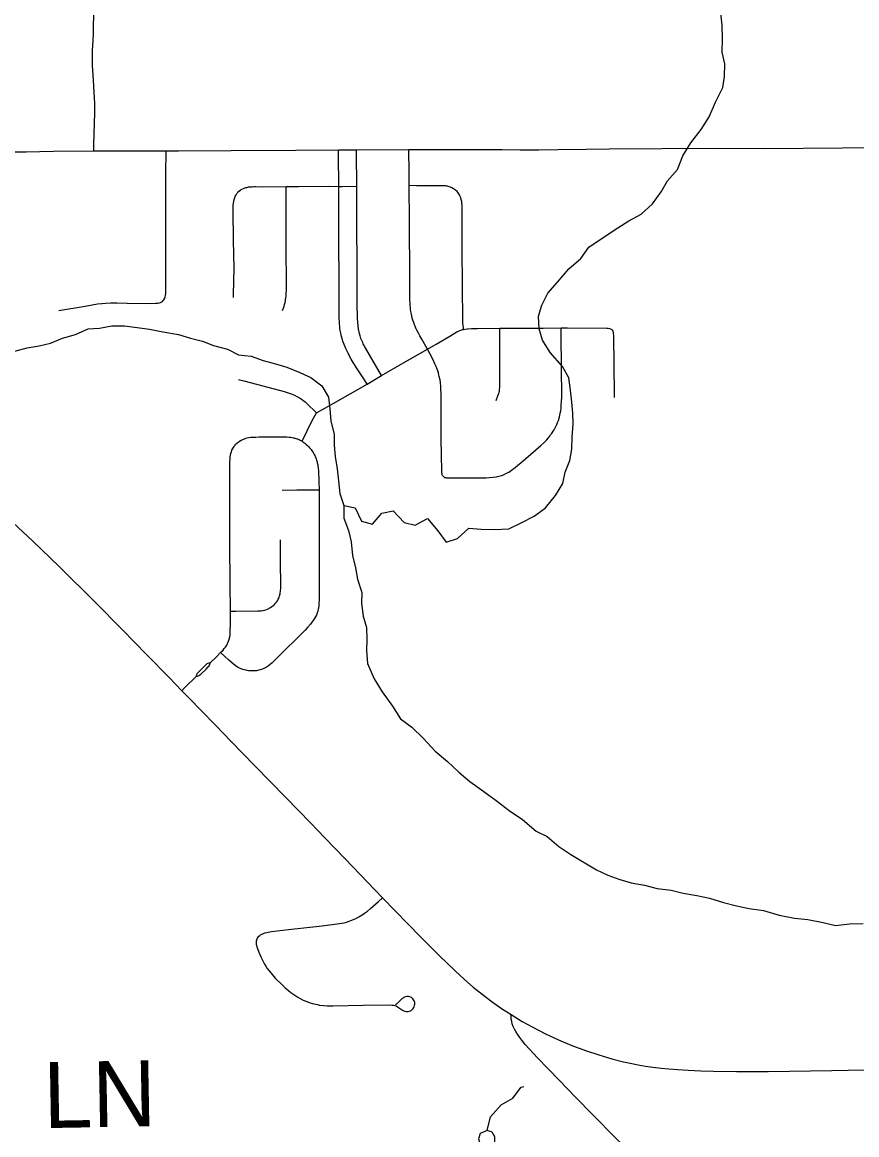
# Model space of a CAD drawing. Extents: x 0 to 34, y 0 to 22.
# Drawn here: x 24.284 to 25.003, y 13.986 to 14.945 of the extents above; entities that cross this region are included whole.
import ezdxf

# ---------------------------------------------------------------- set-up
doc = ezdxf.new("R2010")
doc.units = 0
for name, color, linetype in [('GM_X_County_Road', 7, 'Continuous'), ('GM_X_County_Road_Text', 7, 'Continuous'), ('GM_X_Minor_Lake', 7, 'Continuous'), ('GM_X_Minor_River', 7, 'Continuous'), ('GM_X_State_Route', 7, 'Continuous'), ('GM_X_Township_Road', 7, 'Continuous')]:
    doc.layers.add(name, color=color, linetype=linetype)

msp = doc.modelspace()

# ---------------------------------------------------------------- linework, layer by layer
at = {"layer": 'GM_X_County_Road'}
msp.add_lwpolyline([(24.80457, 13.97386), (24.79456, 13.98403), (24.77577, 14.00299), (24.76063, 14.01855), (24.74635, 14.03327), (24.72773, 14.05246), (24.71728, 14.06389), (24.71509, 14.0665), (24.71251, 14.06988), (24.7105, 14.07286), (24.70904, 14.07511), (24.70787, 14.07717), (24.70687, 14.07942), (24.70607, 14.08178), (24.70558, 14.08381), (24.70525, 14.08589), (24.70502, 14.08982)], dxfattribs=at)
at = {"layer": 'GM_X_Minor_Lake'}
msp.add_lwpolyline([(24.68006, 13.97726), (24.68161, 13.97588), (24.68426, 13.97514), (24.68578, 13.97477), (24.68842, 13.97631), (24.69104, 13.97974), (24.69101, 13.98429), (24.6887, 13.98844), (24.68453, 13.98993), (24.67849, 13.98723), (24.67702, 13.98267), (24.67796, 13.97992)], dxfattribs=at)
at = {"layer": 'GM_X_Minor_River'}
for points in [[(24.56103, 14.52851), (24.57089, 14.52632), (24.57628, 14.51498), (24.58576, 14.5124), (24.59363, 14.52194), (24.60346, 14.52391), (24.613, 14.51375), (24.62248, 14.51155), (24.63303, 14.51731), (24.64182, 14.50676), (24.64909, 14.49696), (24.6589, 14.50007), (24.66868, 14.50887), (24.67928, 14.50819), (24.69101, 14.5079), (24.70312, 14.50837), (24.71368, 14.51338), (24.72499, 14.51915), (24.73477, 14.52643), (24.74339, 14.53712), (24.74974, 14.5474), (24.75156, 14.55727), (24.75564, 14.56716), (24.75745, 14.57703), (24.75775, 14.58727), (24.75842, 14.59865), (24.75834, 14.60813), (24.75751, 14.6176), (24.75629, 14.62783), (24.75469, 14.63843), (24.74932, 14.64825), (24.73862, 14.6603), (24.73211, 14.67086), (24.72938, 14.6807), (24.72853, 14.69169), (24.73148, 14.70119), (24.7367, 14.71147), (24.74495, 14.72101), (24.7547, 14.73246), (24.76523, 14.74126), (24.77196, 14.75117), (24.7938, 14.76574), (24.8066, 14.7738), (24.81715, 14.77957), (24.82692, 14.78837), (24.83441, 14.79866), (24.83964, 14.80818), (24.84826, 14.8181), (24.85309, 14.82989), (24.85981, 14.84094), (24.8688, 14.85238), (24.87553, 14.86343), (24.88111, 14.87598), (24.88744, 14.88854), (24.88888, 14.89803), (24.88917, 14.90903), (24.88682, 14.91925), (24.88711, 14.93063), (24.88701, 14.94238), (24.88579, 14.95261)], [(24.27763, 14.66131), (24.2882, 14.66443), (24.29841, 14.66602), (24.30823, 14.66837), (24.31879, 14.67262), (24.32975, 14.67574), (24.34068, 14.68076), (24.35052, 14.68121), (24.3611, 14.68319), (24.37207, 14.68327), (24.38306, 14.68184), (24.39367, 14.6804), (24.40504, 14.67822), (24.41869, 14.67567), (24.42893, 14.67271), (24.43917, 14.67014), (24.44866, 14.66642), (24.4608, 14.6631), (24.4703, 14.65824), (24.48128, 14.65719), (24.49153, 14.65348), (24.50215, 14.65052), (24.51202, 14.64757), (24.52303, 14.6431), (24.53253, 14.63862), (24.54204, 14.63149), (24.5478, 14.62168), (24.54901, 14.61183), (24.54986, 14.60122), (24.55259, 14.58987), (24.55267, 14.58039), (24.55351, 14.57054), (24.55511, 14.55994), (24.55632, 14.54971), (24.55754, 14.53872), (24.56103, 14.52851), (24.56112, 14.51752), (24.56499, 14.50693), (24.56734, 14.49709), (24.56857, 14.48535), (24.57092, 14.47475), (24.57289, 14.46491), (24.57639, 14.45356), (24.57609, 14.44408), (24.57769, 14.4331), (24.58041, 14.42326), (24.58087, 14.41303), (24.58057, 14.40355), (24.58142, 14.39218), (24.5872, 14.37895), (24.5941, 14.36801), (24.6029, 14.35557), (24.6098, 14.34463), (24.6197, 14.3375), (24.62924, 14.32809), (24.63955, 14.3168), (24.65022, 14.30778), (24.66013, 14.29876), (24.66966, 14.29049), (24.68146, 14.28186), (24.69211, 14.27436), (24.70354, 14.26572), (24.71495, 14.25785), (24.72677, 14.2477), (24.73627, 14.24323)], [(24.73627, 14.24323), (24.74618, 14.23458), (24.75645, 14.22784), (24.77851, 14.21436), (24.78838, 14.20988), (24.79787, 14.20654), (24.8085, 14.20321), (24.81986, 14.2014), (24.83086, 14.19846), (24.84299, 14.19703), (24.85323, 14.19446), (24.86498, 14.19227), (24.87597, 14.19008), (24.88811, 14.18638), (24.89911, 14.18344), (24.9101, 14.18124), (24.92261, 14.17944), (24.93589, 14.17538), (24.94915, 14.17282), (24.96052, 14.17177), (24.97378, 14.16922), (24.9844, 14.16665), (24.9965, 14.16788), (25.00823, 14.16835)], [(24.68453, 13.98993), (24.68746, 14.00171), (24.69647, 14.01201), (24.70664, 14.01778), (24.71375, 14.02731), (24.71602, 14.02771)]]:
    msp.add_lwpolyline(points, dxfattribs=at)
at = {"layer": 'GM_X_State_Route'}
for points in [[(24.27612, 14.51342), (24.29281, 14.49786), (24.3158, 14.47575), (24.34676, 14.44528), (24.37013, 14.4215), (24.39132, 14.39977), (24.41042, 14.38035), (24.42148, 14.36883), (24.4285, 14.36151), (24.43715, 14.35259), (24.45065, 14.33884), (24.46364, 14.32546), (24.48432, 14.30425), (24.51078, 14.27725), (24.53261, 14.25462), (24.54452, 14.24219)], [(24.54452, 14.24219), (24.56203, 14.2239), (24.59426, 14.19023), (24.62702, 14.15663), (24.64335, 14.14046), (24.65678, 14.12754), (24.66497, 14.11996), (24.67247, 14.11347), (24.68019, 14.10726), (24.68875, 14.10088), (24.69689, 14.09512), (24.70502, 14.08982), (24.71456, 14.08392), (24.7232, 14.07907), (24.73475, 14.07312), (24.74599, 14.0679), (24.75744, 14.06317), (24.76908, 14.05889), (24.78051, 14.05511), (24.79185, 14.05173), (24.80189, 14.04917), (24.80772, 14.04786), (24.81447, 14.04645), (24.82096, 14.04538), (24.82721, 14.04448), (24.83445, 14.04357), (24.8409, 14.04298), (24.8486, 14.04241), (24.8576, 14.04188), (24.8685, 14.04141), (24.87932, 14.04106), (24.89919, 14.04072), (24.92652, 14.04081), (24.9812, 14.04166), (25.05143, 14.04294)]]:
    msp.add_lwpolyline(points, dxfattribs=at)
at = {"layer": 'GM_X_Township_Road'}
for points in [[(24.34552, 14.834), (24.34568, 14.8396), (24.34647, 14.86689), (24.34647, 14.87133), (24.3464, 14.87497), (24.34621, 14.87976), (24.34498, 14.89957), (24.34475, 14.90332), (24.34456, 14.90753), (24.3445, 14.90994), (24.34445, 14.91319), (24.34446, 14.91561), (24.34451, 14.91753), (24.34463, 14.92042), (24.34502, 14.92876), (24.34526, 14.93517), (24.34546, 14.94365), (24.34588, 14.95475)], [(24.15556, 14.83308), (24.18625, 14.83308), (24.25271, 14.83314), (24.26824, 14.83324), (24.28747, 14.83335), (24.311, 14.83371), (24.34552, 14.834)], [(24.34552, 14.834), (24.365, 14.83416), (24.3942, 14.83409), (24.40797, 14.83397)], [(24.40471, 14.70439), (24.4054, 14.70508), (24.40588, 14.70567), (24.40666, 14.70704), (24.40708, 14.70812), (24.40747, 14.70972), (24.40761, 14.71081), (24.40769, 14.71218), (24.40772, 14.71545), (24.40778, 14.72412), (24.4077, 14.75948), (24.40757, 14.78273), (24.40775, 14.81204), (24.40775, 14.81696), (24.40793, 14.83114), (24.40797, 14.83397)], [(24.40797, 14.83397), (24.41868, 14.83404), (24.46404, 14.83426), (24.5197, 14.83467), (24.55652, 14.83483)], [(24.55652, 14.83483), (24.57196, 14.83498), (24.61685, 14.83521)], [(24.58094, 14.63311), (24.57867, 14.63664), (24.57199, 14.64704), (24.57008, 14.65005), (24.56916, 14.65155), (24.56744, 14.65444), (24.56584, 14.65726), (24.56458, 14.65968), (24.56271, 14.66364), (24.56119, 14.66712), (24.56017, 14.67004), (24.55981, 14.67121), (24.55927, 14.67313), (24.55903, 14.67408), (24.55834, 14.67702), (24.55793, 14.67922), (24.5576, 14.68162), (24.55742, 14.68321), (24.5573, 14.68447), (24.55714, 14.68696), (24.55702, 14.68922), (24.55693, 14.69192), (24.55684, 14.69619), (24.55686, 14.71306), (24.55678, 14.76446), (24.5566, 14.80349), (24.55653, 14.83073), (24.55652, 14.83483)], [(24.59352, 14.64036), (24.59151, 14.64384), (24.58, 14.66375), (24.57918, 14.66519), (24.57852, 14.66639), (24.57778, 14.66787), (24.57727, 14.66889), (24.57695, 14.66956), (24.57645, 14.67063), (24.57598, 14.67169), (24.57567, 14.67249), (24.57526, 14.67364), (24.57496, 14.67457), (24.57443, 14.67658), (24.5737, 14.68027), (24.57322, 14.68346), (24.57292, 14.68614), (24.57268, 14.68995), (24.5724, 14.70213), (24.57206, 14.8035), (24.57197, 14.83206), (24.57196, 14.83498)], [(24.61685, 14.83521), (24.63145, 14.83517), (24.65941, 14.83516), (24.69734, 14.83513), (24.71287, 14.83505), (24.72896, 14.83493), (24.74549, 14.83513), (24.76968, 14.83549), (24.78957, 14.83568), (24.8805, 14.83633), (24.92309, 14.83613), (24.99049, 14.83667), (25.01908, 14.83689), (25.0932, 14.83659), (25.1496, 14.83666), (25.1554, 14.83676)], [(24.64651, 14.55366), (24.6461, 14.55428), (24.64576, 14.55501), (24.64556, 14.55577), (24.64545, 14.55658), (24.64541, 14.55724), (24.64539, 14.55802), (24.64485, 14.58591), (24.64476, 14.60148), (24.64469, 14.6133), (24.64472, 14.62117), (24.64471, 14.62543), (24.64466, 14.62804), (24.64451, 14.63123), (24.64421, 14.63423), (24.64385, 14.63667), (24.64366, 14.63767), (24.64323, 14.63957), (24.64291, 14.64088), (24.64243, 14.64266), (24.6419, 14.6444), (24.64136, 14.64595), (24.6405, 14.64816), (24.63949, 14.65046), (24.63787, 14.65398), (24.63548, 14.65883), (24.63312, 14.66324), (24.62818, 14.67165), (24.62649, 14.67458), (24.62519, 14.67688), (24.62379, 14.67962), (24.623, 14.68129), (24.62235, 14.68286), (24.62181, 14.68417), (24.62114, 14.68606), (24.62042, 14.68822), (24.6199, 14.68995), (24.61944, 14.692), (24.61896, 14.69442), (24.61876, 14.69561), (24.61853, 14.69726), (24.61839, 14.69847), (24.61819, 14.70134), (24.61797, 14.70701), (24.61789, 14.71047), (24.61789, 14.72697), (24.61776, 14.74613), (24.61765, 14.75163), (24.61758, 14.76702), (24.61758, 14.7732), (24.61732, 14.80408), (24.61719, 14.81978), (24.61695, 14.83083), (24.61685, 14.83521)], [(24.46598, 14.70778), (24.46602, 14.70965), (24.4663, 14.72205), (24.4665, 14.73266), (24.4662, 14.74511), (24.46606, 14.75686), (24.4657, 14.78234), (24.46571, 14.78351), (24.46575, 14.78586), (24.4658, 14.78717), (24.46589, 14.7887), (24.46614, 14.7906), (24.46643, 14.79209), (24.46698, 14.79385), (24.46771, 14.79541), (24.46822, 14.79627), (24.46885, 14.79721), (24.46959, 14.79812), (24.47067, 14.79923), (24.47186, 14.80015), (24.4726, 14.80067), (24.47326, 14.80108), (24.47449, 14.8017), (24.47512, 14.80195), (24.47597, 14.80224), (24.47664, 14.80244), (24.4774, 14.80263), (24.4782, 14.80279), (24.47893, 14.80292), (24.48073, 14.80311), (24.48198, 14.80319), (24.48353, 14.80322), (24.48493, 14.80322), (24.49132, 14.80314), (24.5112, 14.80334), (24.52195, 14.80345), (24.54744, 14.8035), (24.5566, 14.80349), (24.55976, 14.80349), (24.57206, 14.8035)], [(24.50814, 14.69663), (24.50871, 14.69806), (24.50922, 14.69946), (24.50949, 14.70031), (24.5099, 14.70173), (24.51014, 14.70264), (24.51033, 14.70349), (24.51063, 14.70485), (24.51087, 14.70622), (24.511, 14.70719), (24.51119, 14.7088), (24.51127, 14.70962), (24.51136, 14.71076), (24.51157, 14.71435), (24.51167, 14.7178), (24.51143, 14.7522), (24.51133, 14.76734), (24.5112, 14.80047), (24.5112, 14.80334)], [(24.6642, 14.68021), (24.66396, 14.6817), (24.66364, 14.68365), (24.66348, 14.68594), (24.66308, 14.71965), (24.66304, 14.74756), (24.66289, 14.76362), (24.66291, 14.78), (24.66282, 14.78685), (24.66268, 14.789), (24.66254, 14.79033), (24.66219, 14.79211), (24.66178, 14.79349), (24.66104, 14.7953), (24.66051, 14.7963), (24.65943, 14.79787), (24.65848, 14.7989), (24.65705, 14.80024), (24.65629, 14.80083), (24.65557, 14.80134), (24.65407, 14.80222), (24.6528, 14.80283), (24.65185, 14.80319), (24.65036, 14.80355), (24.64955, 14.80371), (24.64865, 14.80381), (24.64797, 14.80387), (24.64664, 14.80392), (24.6237, 14.80404), (24.61732, 14.80408)], [(24.31556, 14.69662), (24.33828, 14.70035), (24.34875, 14.70216), (24.35257, 14.70263), (24.35602, 14.70289), (24.36016, 14.70303), (24.36549, 14.70306), (24.37447, 14.7028)], [(24.37447, 14.7028), (24.39141, 14.70264), (24.39882, 14.70267), (24.39965, 14.7027), (24.40086, 14.70281), (24.40222, 14.70311), (24.40301, 14.7034), (24.40365, 14.70371), (24.40471, 14.70439)], [(24.52497, 14.58385), (24.53383, 14.60172), (24.53741, 14.60826), (24.55166, 14.61622), (24.58094, 14.63311), (24.59352, 14.64036), (24.61591, 14.65328), (24.63312, 14.66324), (24.64064, 14.66758), (24.65238, 14.67451), (24.65831, 14.67801), (24.66033, 14.67903), (24.66163, 14.67955), (24.66358, 14.68009), (24.6642, 14.68021), (24.66525, 14.68042), (24.66742, 14.6807), (24.66822, 14.68076), (24.67101, 14.6809), (24.676, 14.68107), (24.6955, 14.68117), (24.69776, 14.68119), (24.71517, 14.6813), (24.73256, 14.68136), (24.74821, 14.68149), (24.75368, 14.68154), (24.7874, 14.68129), (24.78872, 14.68114), (24.78977, 14.68091), (24.79075, 14.68057), (24.79169, 14.67999)], [(24.64651, 14.55366), (24.6471, 14.55307), (24.64774, 14.55271), (24.64873, 14.5525), (24.64955, 14.55243), (24.65028, 14.5524), (24.65119, 14.55238), (24.65348, 14.55236), (24.66616, 14.55233), (24.6836, 14.55236), (24.6865, 14.5525), (24.68974, 14.55274), (24.69223, 14.55309), (24.69459, 14.5536), (24.69666, 14.55425), (24.69855, 14.55497), (24.70066, 14.55596), (24.70303, 14.55732), (24.70548, 14.55894), (24.70858, 14.56123), (24.71091, 14.56313), (24.71347, 14.56531), (24.73055, 14.58008), (24.73315, 14.58252), (24.7357, 14.58509), (24.73701, 14.58658), (24.73835, 14.58822), (24.73913, 14.58921), (24.73981, 14.59013), (24.74052, 14.59119), (24.74135, 14.59246), (24.74214, 14.59371), (24.74281, 14.59484), (24.74371, 14.59659), (24.74449, 14.59833), (24.74517, 14.59999), (24.74575, 14.60171), (24.74673, 14.60473), (24.7471, 14.60627), (24.74746, 14.60806), (24.74779, 14.60998), (24.74805, 14.61228), (24.74831, 14.61514), (24.7485, 14.61807), (24.74867, 14.62177), (24.74875, 14.62507), (24.74851, 14.64477), (24.74824, 14.67778), (24.74821, 14.68149)], [(24.69218, 14.61887), (24.69374, 14.62296), (24.69422, 14.62428), (24.69445, 14.62503), (24.69476, 14.62613), (24.69493, 14.62689), (24.69507, 14.62767), (24.69519, 14.62859), (24.6953, 14.62992), (24.69536, 14.63116), (24.6954, 14.63269), (24.69542, 14.6334), (24.69543, 14.63503), (24.69537, 14.66037), (24.69548, 14.67853), (24.6955, 14.68117)], [(24.79421, 14.62164), (24.79417, 14.62411), (24.79346, 14.67495), (24.79339, 14.67657), (24.79325, 14.67758), (24.79298, 14.67844), (24.79256, 14.67912), (24.79169, 14.67999)], [(24.47033, 14.63705), (24.47476, 14.63598), (24.50649, 14.62756), (24.50953, 14.62669), (24.51309, 14.62558), (24.51549, 14.6247), (24.51835, 14.62347), (24.52048, 14.62241), (24.52413, 14.62035), (24.52566, 14.61932), (24.5276, 14.61789), (24.52922, 14.61645), (24.53741, 14.60826)], [(24.46325, 14.43733), (24.46312, 14.46125), (24.46288, 14.49484), (24.4628, 14.54895), (24.46281, 14.56377), (24.46289, 14.56651), (24.46296, 14.5679), (24.46302, 14.56909), (24.46318, 14.57041), (24.46339, 14.57175), (24.46374, 14.57336), (24.46415, 14.5747), (24.46464, 14.576), (24.46547, 14.57769), (24.46594, 14.57848), (24.46645, 14.57923), (24.46686, 14.57982), (24.46746, 14.58057), (24.46803, 14.58122), (24.46886, 14.58204), (24.4698, 14.58286), (24.47109, 14.58382), (24.47251, 14.58465), (24.47479, 14.58575), (24.47656, 14.58643), (24.47782, 14.58681), (24.47905, 14.58706), (24.48074, 14.58729), (24.48203, 14.58741), (24.48387, 14.58748), (24.48511, 14.58748), (24.48808, 14.58752), (24.4954, 14.58764), (24.50375, 14.58762), (24.50892, 14.58758), (24.51181, 14.58749), (24.51396, 14.58736), (24.51507, 14.58724), (24.51632, 14.58707), (24.51734, 14.58688), (24.51806, 14.5867), (24.51889, 14.58647), (24.51975, 14.58622), (24.5204, 14.58601), (24.52102, 14.58579), (24.52243, 14.58522), (24.52351, 14.58471), (24.52497, 14.58385)], [(24.52497, 14.58385), (24.52581, 14.5833), (24.5274, 14.58207), (24.52859, 14.58106), (24.52966, 14.5801), (24.53077, 14.57898), (24.53142, 14.57826), (24.53229, 14.57724), (24.53276, 14.57666), (24.53368, 14.57541), (24.53456, 14.57406), (24.53549, 14.5725), (24.53593, 14.57162), (24.53643, 14.5705), (24.5368, 14.56955), (24.53716, 14.56861), (24.5375, 14.56763), (24.53795, 14.56605), (24.53815, 14.56521), (24.53848, 14.56363), (24.53873, 14.56211), (24.53883, 14.5614), (24.53897, 14.56016), (24.53909, 14.55886), (24.53928, 14.55568), (24.53943, 14.5522), (24.53953, 14.54891), (24.53965, 14.54208)], [(24.53965, 14.54208), (24.5397, 14.53181), (24.53966, 14.48713), (24.53976, 14.46662), (24.53978, 14.45746), (24.5397, 14.45006), (24.53963, 14.44625), (24.53956, 14.44446), (24.53949, 14.44331), (24.53936, 14.44186), (24.53913, 14.44007), (24.53894, 14.43916), (24.5387, 14.43811), (24.53846, 14.43721), (24.5381, 14.43608), (24.53731, 14.43405), (24.53679, 14.43297), (24.53513, 14.43015), (24.53354, 14.42785), (24.53217, 14.42611), (24.52976, 14.42339), (24.52761, 14.42111), (24.5028, 14.39626), (24.49915, 14.39291), (24.49742, 14.39145), (24.49599, 14.39039), (24.49435, 14.38927), (24.49315, 14.38856), (24.49159, 14.38777), (24.49011, 14.38717), (24.48872, 14.38674), (24.48576, 14.38604), (24.4834, 14.38586), (24.48151, 14.38586), (24.48034, 14.38595), (24.4789, 14.38612), (24.47761, 14.3863), (24.47674, 14.38645), (24.47518, 14.38679), (24.47407, 14.38711), (24.47254, 14.38764), (24.47109, 14.3883), (24.46936, 14.38924), (24.46732, 14.3906), (24.4656, 14.39188), (24.46193, 14.39507), (24.45808, 14.39866), (24.45536, 14.4012)], [(24.508, 14.54169), (24.52054, 14.54194), (24.53552, 14.54205), (24.53965, 14.54208)], [(24.46325, 14.43733), (24.46801, 14.43738), (24.48685, 14.43756), (24.48849, 14.43762), (24.48956, 14.43772), (24.49084, 14.43788), (24.49149, 14.43801), (24.4926, 14.43828), (24.49368, 14.43862), (24.49515, 14.43925), (24.49769, 14.44059), (24.49899, 14.44143), (24.49992, 14.44212), (24.50126, 14.44328), (24.5022, 14.44425), (24.50295, 14.44517), (24.50375, 14.4463), (24.50454, 14.44773), (24.50493, 14.44853), (24.5053, 14.44949), (24.50568, 14.45066), (24.50587, 14.45134), (24.5061, 14.45241), (24.50626, 14.45333), (24.50639, 14.45427), (24.50649, 14.45552), (24.50658, 14.45671), (24.50664, 14.45823), (24.50667, 14.45934), (24.50669, 14.46105), (24.50669, 14.46406), (24.50653, 14.47542), (24.50653, 14.49891)], [(24.45486, 14.40166), (24.45541, 14.40222), (24.45695, 14.40388), (24.45797, 14.4051), (24.45899, 14.40639), (24.4602, 14.40818), (24.46089, 14.40941), (24.46178, 14.41149), (24.46233, 14.41315), (24.46284, 14.41532), (24.46304, 14.41672), (24.46321, 14.41929), (24.4633, 14.42765), (24.46325, 14.43733)], [(24.43397, 14.38128), (24.43486, 14.38144), (24.43615, 14.38191), (24.43703, 14.38241), (24.4379, 14.3831), (24.44234, 14.38744), (24.44413, 14.38934), (24.44461, 14.38984), (24.44509, 14.39047), (24.44558, 14.39137), (24.44578, 14.39224), (24.44582, 14.39294), (24.45093, 14.39776), (24.45486, 14.40166)], [(24.43397, 14.38128), (24.43407, 14.38195), (24.43422, 14.38256), (24.43471, 14.38358), (24.43527, 14.38432), (24.44279, 14.39172), (24.44336, 14.39216), (24.4439, 14.39249), (24.44469, 14.39279), (24.44582, 14.39294)], [(24.42148, 14.36883), (24.42385, 14.3712), (24.43397, 14.38128)], [(24.4863, 14.15545), (24.48706, 14.1565), (24.48785, 14.15735), (24.48861, 14.15804), (24.48961, 14.15873), (24.49037, 14.15916), (24.49094, 14.15945), (24.49167, 14.15976), (24.4929, 14.16013), (24.49477, 14.16061), (24.49583, 14.16083), (24.49858, 14.16124), (24.51319, 14.16295), (24.54222, 14.1661), (24.55714, 14.16813), (24.56119, 14.16893), (24.56341, 14.16947), (24.56569, 14.1702), (24.5671, 14.17074), (24.56922, 14.17163), (24.57127, 14.17255), (24.57399, 14.174), (24.57665, 14.1756), (24.57888, 14.1771), (24.58127, 14.17892), (24.58408, 14.18126), (24.59093, 14.1873), (24.59426, 14.19023)], [(24.4863, 14.15545), (24.486, 14.15479), (24.4857, 14.15399), (24.48548, 14.15294), (24.48544, 14.15177), (24.48556, 14.15047), (24.48576, 14.14955), (24.48618, 14.14811), (24.48667, 14.14662), (24.48787, 14.14347), (24.48947, 14.1396), (24.49087, 14.13661), (24.49268, 14.13326), (24.49379, 14.13149), (24.49508, 14.12957), (24.49689, 14.12708), (24.49798, 14.12569), (24.50039, 14.12287), (24.50222, 14.12092), (24.50792, 14.11529), (24.51052, 14.11287), (24.51328, 14.11045), (24.51527, 14.10889), (24.51879, 14.1064), (24.52126, 14.10484), (24.5233, 14.10361), (24.52592, 14.10229), (24.52834, 14.10123), (24.53209, 14.09987), (24.53411, 14.09925), (24.53817, 14.09831), (24.54009, 14.09796), (24.54366, 14.09751), (24.54662, 14.0973), (24.55142, 14.09722), (24.5776, 14.09773), (24.60133, 14.09803), (24.60255, 14.09796), (24.60389, 14.09781), (24.60499, 14.09755), (24.60604, 14.09715), (24.60709, 14.09655), (24.6106, 14.0941), (24.61144, 14.09358), (24.61218, 14.09317), (24.6128, 14.09291), (24.61367, 14.09263), (24.61469, 14.09243), (24.61531, 14.09237), (24.61646, 14.09244), (24.61712, 14.09258), (24.6183, 14.09297), (24.61887, 14.09328), (24.61957, 14.09377), (24.62021, 14.09435), (24.6206, 14.09486), (24.62129, 14.09594), (24.62161, 14.09669), (24.62193, 14.09776), (24.62206, 14.0986), (24.62205, 14.09939), (24.622, 14.10019), (24.62179, 14.10103), (24.62154, 14.10167), (24.62102, 14.10255), (24.62029, 14.10336), (24.61974, 14.10388), (24.61914, 14.10433), (24.61849, 14.10471), (24.61781, 14.10497), (24.61678, 14.10524), (24.6161, 14.10532), (24.61512, 14.10533), (24.61422, 14.10515), (24.61336, 14.10482), (24.6127, 14.10451), (24.61209, 14.10415), (24.61143, 14.10368), (24.61084, 14.10321), (24.60983, 14.10226), (24.60836, 14.1008), (24.60748, 14.09984), (24.60642, 14.09883), (24.60552, 14.09808)]]:
    msp.add_lwpolyline(points, dxfattribs=at)

# ---------------------------------------------------------------- texts
at = {"layer": 'GM_X_County_Road_Text'}
msp.add_text('LN', height=0.056818, rotation=1.03168, dxfattribs=at).set_placement((24.30256, 13.99187))

doc.saveas('drawing.dxf')
